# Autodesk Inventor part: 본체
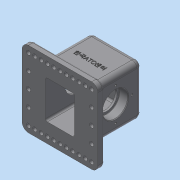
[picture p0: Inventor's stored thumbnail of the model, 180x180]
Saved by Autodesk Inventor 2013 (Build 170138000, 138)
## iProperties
Created: 2018-11
Part Number: 본체
Material: 일반
Document SubType Name: Modeling
Designer: dgall
Density: 1 g/cm^3
Author: dgall
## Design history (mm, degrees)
sketch "스케치1"
  geometry: L1 (-40, 45)-(40, 45); L2 (40, 45)-(40, -45); L3 (40, -45)-(-40, -45); L4 (-40, -45)-(-40, 45); 3 further points
  constraints: 8 end point, 2 midpoint, 2 parallel, 1 horizontal, 1 horizontal alignment, 1 perpendicular, 1 vertical alignment
  dimensions: "d0" = 80 distance of L1.start L1.end; "d2" = 90 distance of L1.end L2.end
extrude "돌출1" new body sketch "스케치1" stored distance "d3" = 80; taper "d4" = 0 deg
sketch "스케치2"
  geometry: L1 (-20, 20)-(100, 20); L2 (100, 20)-(100, -100); L3 (100, -100)-(-20, -100); L4 (-20, -100)-(-20, 20); 8 further points
  constraints: 8 end point, 5 vertical alignment, 2 midpoint, 2 parallel, 1 horizontal, 1 horizontal alignment, 1 perpendicular
  dimensions: "d5" = 120 distance of L1.start L1.end; "d7" = 120 distance of L1.end L2.end; "d8" = 10 horizontal distance of L1.start point (-10, 10); "d9" = 10 horizontal distance of L1.start point (-10, 10); "d10" = 25 distance of point (-10, -15) point (-10, 10); "d11" = 25 distance of point (-10, -15) point (-10, -40); "d12" = 25 distance of point (-10, -40) point (-10, -65); "d13" = 25 distance of point (-10, -65) point (-10, -90)
extrude "돌출2" join sketch "스케치2" distance "d14" = 10; taper "d15" = 0 deg
hole "구멍1" sketch "스케치2" diameter "d16" = 6.6; stored, may be unused: countersink angle "d20" = 90 deg, drill point angle "d22" = 118 deg; dims "d17" = 6, "d18" = 4, "d19" = 2, "d21" = 8
sketch "스케치3"
  geometry: L1 (37, -30)-(83, -30); L2 (83, -30)-(83, -90); L3 (83, -90)-(37, -90); L4 (37, -90)-(37, -30); 3 further points
  constraints: 8 end point, 2 midpoint, 2 parallel, 1 horizontal, 1 horizontal alignment, 1 perpendicular, 1 vertical alignment
  dimensions: "d23" = 60 distance of L1.end L2.end; "d25" = 46 distance of L1.start L1.end
extrude "돌출3" cut sketch "스케치3" distance "d26" = 80; taper "d27" = 0 deg
sketch "스케치4"
  geometry: L1 (0, -120)-(0, 0) reference; 11 further points
  constraints: 9 horizontal alignment
  dimensions: "d28" = 20 distance from line of L1 point (20, -110); "d29" = 10 vertical distance of L1.start point (20, -110); "d30" = 10 distance of point (30, -110) point (20, -110); "d31" = 10 distance of point (30, -110) point (40, -110); "d32" = 10 distance of point (40, -110) point (50, -110); "d33" = 10 distance of point (50, -110) point (60, -110); "d34" = 10 distance of point (60, -110) point (70, -110); "d35" = 10 distance of point (70, -110) point (80, -110); "d36" = 10 distance of point (80, -110) point (90, -110); "d37" = 10 distance of point (100, -110) point (90, -110); "d38" = 10 distance of point (100, -110) point (110, -110)
hole "구멍2" sketch "스케치4" at (20, -110), (30, -110), (40, -110), (50, -110), (60, -110), (70, -110), (80, -110), (90, -110), (100, -110), (110, -110) diameter "d39" = 6.6; stored, may be unused: countersink angle "d43" = 90 deg, drill point angle "d45" = 118 deg; dims "d40" = 6, "d41" = 4, "d42" = 2, "d44" = 8
node "작업 평면1"
node "작업 평면2"
sketch "스케치5"
  geometry: L1 (-20, -90)-(100, -90) reference; C1 r 20 at (40, -42); 1 further point
  constraints: 1 centre point, 1 vertical alignment
  dimensions: "d46" = 40 diameter of C1; "d47" = 48 distance from line of L1 C1.centre
extrude "돌출4" cut sketch "스케치5" distance "d48" = 14; taper "d49" = 0 deg
sketch "스케치6"
  geometry: C1 r 20 at (0, 0) reference; C2 r 16.5 at (0, 0); 1 further point
  constraints: 1 centre point, 1 coincident
  dimensions: "d50" = 33 diameter of C2
extrude "돌출5" cut sketch "스케치6" distance "d51" = 3; taper "d52" = 0 deg
fillet "모깎기1" dims "d53" = 8
fillet "모깎기2" dims "d54" = 8
fillet "모깎기3" dims "d55" = 3
fillet "모깎기4" dims "d56" = 10
fillet "모깎기5" dims "d57" = 3
node "작업 평면3"
sketch "스케치7"
  geometry: C1 r 7.5 at (0, 0); 1 further point
  constraints: 1 centre point, 1 coincident
  dimensions: "d59" = 15 diameter of C1
extrude "돌출6" join sketch "스케치7" stored distance "d60" = 3; taper "d61" = 0 deg
hole "구멍3" diameter "d64" = 4.917; stored, may be unused: countersink angle "d68" = 90 deg, drill point angle "d70" = 118 deg; dims "d65" = 6, "d66" = 4, "d67" = 2, "d69" = 8, "d93" = 10, "d94" = 10
fillet "모깎기6" dims "d71" = 3
fillet "모깎기7" dims "d72" = 3
fillet "모깎기8" dims "d73" = 0.6
chamfer "모따기1" distance "d74" = 1; stored, may be unused: second distance "d75" = 2, angle "d76" = 45 deg
sketch "스케치8"
  geometry: C1 r 16.5 at (32, -34) reference; 2 further points
  constraints: 1 vertical alignment
  dimensions: "d85" = 26 distance of C1.centre point (32, -8)
hole "구멍4" sketch "스케치8" at (32, -8) diameter "d78" = 3.242; stored, may be unused: countersink angle "d82" = 90 deg, drill point angle "d84" = 118 deg; dims "d79" = 8, "d80" = 4, "d81" = 2, "d83" = 10
fillet "모깎기9" dims "d89" = 3
sketch "스케치9"
  geometry: L1 (-50, -45)-(50, -45) reference; 2 further points
  constraints: 1 vertical alignment, 1 other
  dimensions: "d90" = 48 distance from line of L1 point (0, 3)
feature "엠보싱1" sketch "스케치9" dims "d19" = 2, "d91" = 0.5, "d92" = 0
node "솔리드1"
mirror "대칭1"
mirror "대칭2"
mirror "대칭3"
pattern_circular "원형 패턴1" dims angle "d87" = 360 deg
mirror "대칭4"
